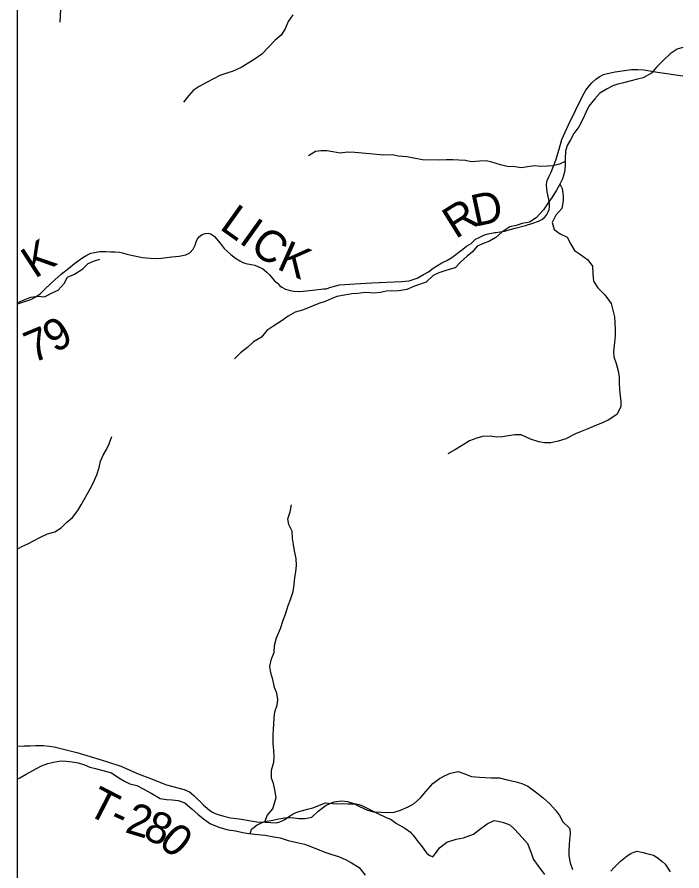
# Model space of a CAD drawing. Extents: x 0 to 82.7, y -0.2 to 22.
# Drawn here: x 2.1 to 3.292, y 15.035 to 16.567 of the extents above; entities that cross this region are included whole.
import ezdxf

# ---------------------------------------------------------------- set-up
doc = ezdxf.new("R2010")
doc.units = 0
for name, color, linetype in [('GM_X_County_Text', 7, 'Continuous'), ('GM_X_Minor_River', 7, 'Continuous'), ('GM_X_Township_Road', 7, 'Continuous'), ('GM_X_Township_Road_Text', 7, 'Continuous'), ('GM_X_Township_Text', 7, 'Continuous'), ('SH_Cut_Line', 7, 'Continuous'), ('SH_Data', 7, 'Continuous')]:
    doc.layers.add(name, color=color, linetype=linetype)

msp = doc.modelspace()

# ---------------------------------------------------------------- linework, layer by layer
at = {"layer": 'GM_X_Minor_River'}
for points in [[(2.3003, 16.7593), (2.2927, 16.7519), (2.2802, 16.7417), (2.2703, 16.7365), (2.2589, 16.7286), (2.2494, 16.718), (2.241, 16.7059), (2.2299, 16.6912), (2.2253, 16.6776), (2.2143, 16.664), (2.2033, 16.6576), (2.1918, 16.6436), (2.1865, 16.6338), (2.1834, 16.6232), (2.1795, 16.6084), (2.1772, 16.5944), (2.1778, 16.5808), (2.177, 16.5698), (2.1769, 16.558)], [(2.5945, 16.5714), (2.5857, 16.5593), (2.5807, 16.5465), (2.5735, 16.5351), (2.5628, 16.5257), (2.5507, 16.5136), (2.5385, 16.5008), (2.5248, 16.4914), (2.5123, 16.4832), (2.502, 16.4768), (2.4876, 16.4704), (2.4781, 16.4674), (2.4634, 16.4626), (2.4406, 16.4506), (2.4266, 16.4427), (2.4159, 16.4356), (2.4076, 16.4258), (2.3984, 16.4144)], [(3.2933, 16.5129), (3.2835, 16.51), (3.271, 16.5013), (3.2584, 16.4896), (3.2462, 16.4772), (3.2375, 16.467), (3.2223, 16.4584), (3.2125, 16.4562), (3.1984, 16.4524), (3.1871, 16.4495), (3.1772, 16.4469), (3.1678, 16.4439), (3.1579, 16.4387), (3.145, 16.4311), (3.1358, 16.4206), (3.1248, 16.4074), (3.1194, 16.3964), (3.1144, 16.3843), (3.1072, 16.3703), (3.0984, 16.3586), (3.0919, 16.3473), (3.0862, 16.3367), (3.0835, 16.3268), (3.0826, 16.3128), (3.0829, 16.3003), (3.0813, 16.2893), (3.0779, 16.2772), (3.0729, 16.2674), (3.0671, 16.2568), (3.0595, 16.2439), (3.0523, 16.2341), (3.0439, 16.2213), (3.0309, 16.2073), (3.0188, 16.1994), (3.0055, 16.1968), (2.9949, 16.1935), (2.9832, 16.1909), (2.9691, 16.1815), (2.9585, 16.1721), (2.9471, 16.165), (2.9376, 16.1616), (2.9251, 16.1564), (2.9167, 16.1462), (2.9072, 16.1386), (2.8947, 16.1277), (2.8852, 16.1172), (2.8704, 16.1131), (2.8564, 16.1082), (2.8457, 16.1034), (2.8336, 16.0917), (2.8123, 16.0842), (2.7987, 16.0786), (2.7847, 16.0764), (2.7624, 16.0758), (2.7514, 16.0732), (2.74, 16.0721), (2.7245, 16.0734), (2.7102, 16.0712), (2.7, 16.0705), (2.6867, 16.0683), (2.6731, 16.0657), (2.6628, 16.0616), (2.6522, 16.0567), (2.6412, 16.0534), (2.628, 16.0478), (2.6117, 16.0414), (2.5988, 16.0377), (2.5859, 16.0306), (2.5733, 16.0216), (2.5604, 16.0133), (2.5479, 16.0047), (2.538, 15.993), (2.524, 15.9843), (2.5137, 15.9753), (2.5004, 15.9647), (2.4897, 15.9542)], [(3.0827, 16.3082), (3.0724, 16.3034), (3.0606, 16.3004), (3.0508, 16.2997), (3.0383, 16.2994), (3.0285, 16.3002), (3.0148, 16.2984), (3.0046, 16.297), (2.9925, 16.2986), (2.9785, 16.2994), (2.9668, 16.3021), (2.9514, 16.3068), (2.9408, 16.3091), (2.9294, 16.3088), (2.9139, 16.3078), (2.9037, 16.3097), (2.892, 16.3106), (2.8811, 16.311), (2.8701, 16.3111), (2.858, 16.3108), (2.827, 16.3109), (2.8141, 16.3137), (2.7986, 16.3164), (2.7835, 16.318), (2.7733, 16.32), (2.7574, 16.3197), (2.7318, 16.3221), (2.7185, 16.3234), (2.7057, 16.3246), (2.6921, 16.3247), (2.6792, 16.3232), (2.666, 16.3256), (2.6554, 16.3272), (2.6448, 16.3276), (2.635, 16.3261), (2.6224, 16.3183)], [(3.0732, 16.268), (3.0774, 16.2597), (3.0792, 16.2468), (3.0791, 16.2374), (3.0764, 16.2237), (3.0661, 16.2116), (3.0592, 16.1988), (3.0626, 16.1863), (3.0735, 16.1782), (3.0863, 16.1725), (3.0926, 16.1599), (3.0994, 16.1485), (3.1099, 16.1412), (3.1235, 16.132), (3.1314, 16.1202), (3.132, 16.1066), (3.1335, 16.0937), (3.1409, 16.0815), (3.1537, 16.0689), (3.165, 16.0533), (3.1672, 16.0438), (3.1709, 16.0297), (3.1716, 16.0187), (3.1722, 16.0062), (3.1722, 15.9956), (3.171, 15.9831), (3.1694, 15.9671), (3.1701, 15.9577), (3.1738, 15.9459), (3.1778, 15.9326), (3.1797, 15.9212), (3.1796, 15.9113), (3.1799, 15.8988), (3.181, 15.8878), (3.1824, 15.8776), (3.1827, 15.8681), (3.1751, 15.8541), (3.1595, 15.8443), (3.1463, 15.8383), (3.1356, 15.8338), (3.1231, 15.8286), (3.1114, 15.8234), (3.1011, 15.8193), (3.0837, 15.8103), (3.0701, 15.8062), (3.0568, 15.8032), (3.0458, 15.8033), (3.0353, 15.8052), (3.0202, 15.8099), (3.0036, 15.8176), (2.9922, 15.8176), (2.9805, 15.8158), (2.9706, 15.814), (2.9593, 15.8137), (2.9483, 15.8156), (2.9343, 15.8146), (2.9241, 15.812), (2.9112, 15.8071), (2.8998, 15.7996), (2.8862, 15.7914), (2.8721, 15.7839)], [(2.1, 16.0547), (2.1111, 16.0593), (2.1247, 16.0645), (2.1369, 16.0667), (2.149, 16.0651), (2.1641, 16.073), (2.1736, 16.0775), (2.1843, 16.0892), (2.1904, 16.1005), (2.2029, 16.1061), (2.2177, 16.1155), (2.2276, 16.1253), (2.2371, 16.1291), (2.2481, 16.1328)], [(2.1, 15.6127), (2.1084, 15.6174), (2.119, 15.6219), (2.1296, 15.6275), (2.141, 15.6335), (2.1543, 15.6399), (2.1679, 15.6436), (2.1789, 15.6511), (2.1892, 15.6609), (2.1995, 15.6692), (2.209, 15.682), (2.2151, 15.6919), (2.2201, 15.7017), (2.2308, 15.7206), (2.2365, 15.7308), (2.243, 15.7459), (2.2469, 15.7588), (2.2496, 15.7702), (2.2542, 15.7811), (2.26, 15.7914), (2.2649, 15.8016), (2.2696, 15.8148)], [(2.5447, 15.1242), (2.5486, 15.1346), (2.5585, 15.1463), (2.5612, 15.1565), (2.5647, 15.1671), (2.5621, 15.1808), (2.5599, 15.1918), (2.5562, 15.2013), (2.5559, 15.2157), (2.5602, 15.2301), (2.561, 15.2403), (2.5603, 15.251), (2.5589, 15.2639), (2.5589, 15.2787), (2.5598, 15.2893), (2.5602, 15.2987), (2.561, 15.3101), (2.5619, 15.3204), (2.5661, 15.3325), (2.5673, 15.3427), (2.5658, 15.3541), (2.5617, 15.3644), (2.5584, 15.3788), (2.5551, 15.3906), (2.5529, 15.4023), (2.5564, 15.4156), (2.5606, 15.4269), (2.5615, 15.4395), (2.5653, 15.4535), (2.5722, 15.4701), (2.5772, 15.4853), (2.5811, 15.4958), (2.5861, 15.5117), (2.5903, 15.5223), (2.5949, 15.5363), (2.5965, 15.5489), (2.5977, 15.5614), (2.5997, 15.5716), (2.6009, 15.583), (2.6006, 15.5959), (2.5973, 15.6095), (2.5955, 15.6209), (2.5936, 15.6316), (2.593, 15.6448), (2.5874, 15.657), (2.5855, 15.6669), (2.5894, 15.6794), (2.5917, 15.6922)], [(2.1, 15.1999), (2.1051, 15.2021), (2.1161, 15.2085), (2.1282, 15.2156), (2.1438, 15.2235), (2.1551, 15.228), (2.1654, 15.2306), (2.1782, 15.2328), (2.1881, 15.2323), (2.1987, 15.2311), (2.2092, 15.2292), (2.2206, 15.2253), (2.2304, 15.2215), (2.2406, 15.2191), (2.2692, 15.2114), (2.2824, 15.2022), (2.2926, 15.1964), (2.3024, 15.1915), (2.3145, 15.1883), (2.3262, 15.1826), (2.3405, 15.1745), (2.3567, 15.1653), (2.368, 15.1634), (2.3779, 15.1626), (2.3888, 15.1617), (2.4005, 15.1575), (2.4137, 15.146), (2.4238, 15.1369), (2.434, 15.1288), (2.4468, 15.1197), (2.4634, 15.1131), (2.4785, 15.1088), (2.4913, 15.1069), (2.5049, 15.1041), (2.5155, 15.1022), (2.5318, 15.1006), (2.545, 15.0993), (2.5601, 15.0966), (2.5714, 15.0943), (2.5861, 15.0896), (2.6043, 15.0857), (2.6152, 15.0834), (2.6269, 15.0791), (2.6367, 15.0745), (2.6533, 15.068), (2.6643, 15.0649), (2.6764, 15.061), (2.6888, 15.0556), (2.6997, 15.0495), (2.7133, 15.0411), (2.7238, 15.0277)], [(2.5177, 15.102), (2.5205, 15.1101), (2.5304, 15.118), (2.5433, 15.124), (2.5557, 15.1254), (2.5694, 15.1284), (2.5796, 15.1302), (2.5917, 15.1309), (2.6049, 15.1293), (2.6166, 15.1293), (2.6284, 15.1318), (2.6398, 15.1424), (2.6542, 15.1529), (2.6686, 15.1589), (2.6815, 15.1607), (2.6921, 15.1595), (2.7038, 15.1564), (2.7136, 15.151), (2.7283, 15.1441), (2.7389, 15.1414), (2.7525, 15.1406), (2.7646, 15.1401), (2.7759, 15.1404), (2.7873, 15.1441), (2.8013, 15.1501), (2.8116, 15.1561), (2.823, 15.1663), (2.8329, 15.1776), (2.8451, 15.192), (2.8576, 15.201), (2.8675, 15.2062), (2.8769, 15.2107), (2.8909, 15.2137), (2.9008, 15.2102), (2.9147, 15.2048), (2.9291, 15.2036), (2.9389, 15.2028), (2.9502, 15.2023), (2.965, 15.2019), (2.9786, 15.1984), (2.9922, 15.1956), (3.005, 15.1921), (3.0156, 15.1875), (3.0295, 15.1772), (3.043, 15.1665), (3.0551, 15.1554), (3.0652, 15.1444), (3.0723, 15.1345), (3.0787, 15.1234), (3.0911, 15.1112), (3.0918, 15.1013), (3.0906, 15.0915), (3.0898, 15.0816), (3.089, 15.0722), (3.0889, 15.0623), (3.0915, 15.0498), (3.0956, 15.0376)]]:
    msp.add_lwpolyline(points, dxfattribs=at)
at = {"layer": 'GM_X_Township_Road'}
for points in [[(2.9586, 16.1808), (2.974, 16.1831), (2.9929, 16.1883), (3.0115, 16.1933), (3.0247, 16.1977), (3.0347, 16.2011), (3.0408, 16.204), (3.046, 16.2084), (3.0496, 16.2128), (3.0521, 16.2176), (3.0538, 16.2222), (3.0548, 16.2268), (3.0546, 16.2321), (3.0534, 16.2402), (3.0502, 16.2538), (3.0498, 16.2593), (3.0493, 16.2669), (3.0504, 16.2742), (3.0532, 16.2809), (3.0573, 16.289), (3.0657, 16.3104), (3.0718, 16.3303), (3.0768, 16.3474), (3.0888, 16.3738), (3.1135, 16.4253), (3.1197, 16.4362), (3.126, 16.4446), (3.1302, 16.4494), (3.1373, 16.4559), (3.1434, 16.4601), (3.1511, 16.4641), (3.1583, 16.4664), (3.1725, 16.4689), (3.2016, 16.4733), (3.2129, 16.4735), (3.2238, 16.4729), (3.2479, 16.4687), (3.2937, 16.462)], [(2.5672, 16.089), (2.5705, 16.0857), (2.5749, 16.0828), (2.5814, 16.0792), (2.5898, 16.0765), (2.5961, 16.0755), (2.6045, 16.075), (2.6126, 16.0757), (2.6298, 16.0775), (2.6495, 16.0796), (2.6543, 16.0796), (2.6627, 16.0826), (2.6715, 16.0851), (2.6782, 16.0868), (2.6878, 16.0876), (2.7054, 16.0884), (2.7359, 16.0905), (2.7891, 16.093), (2.796, 16.0933), (2.8027, 16.0941), (2.8099, 16.0962), (2.817, 16.0989), (2.8289, 16.1052), (2.8377, 16.1104), (2.8459, 16.1165), (2.8538, 16.1215), (2.8616, 16.1262), (2.8704, 16.1307), (2.8775, 16.1345), (2.8844, 16.1393), (2.8919, 16.1452), (2.8991, 16.1508), (2.906, 16.1565), (2.9141, 16.1609), (2.922, 16.1687), (2.9296, 16.1724), (2.9382, 16.1764), (2.9443, 16.1785), (2.9504, 16.1793), (2.9566, 16.1806), (2.9586, 16.1808)], [(2.1, 16.0519), (2.1045, 16.0537), (2.1244, 16.0608), (2.1336, 16.0654), (2.1413, 16.0706), (2.1493, 16.0782), (2.1612, 16.0897), (2.1675, 16.096), (2.1788, 16.1062), (2.193, 16.1167), (2.2031, 16.1251), (2.2177, 16.136), (2.2249, 16.1404), (2.2322, 16.1435), (2.2389, 16.145), (2.2477, 16.1464), (2.259, 16.1469), (2.268, 16.1462), (2.2753, 16.146), (2.2839, 16.1454), (2.2891, 16.1445), (2.2965, 16.1422), (2.3073, 16.1397), (2.3247, 16.1362), (2.3394, 16.1345), (2.3492, 16.1341), (2.3582, 16.1345), (2.3676, 16.1362), (2.3777, 16.1374), (2.3907, 16.1383), (2.4024, 16.141), (2.4099, 16.1441), (2.4154, 16.151), (2.4194, 16.158), (2.4208, 16.164), (2.4233, 16.1695), (2.4273, 16.1739), (2.4321, 16.1772), (2.4372, 16.1787), (2.4426, 16.1793), (2.4474, 16.1785), (2.4539, 16.1737), (2.4642, 16.1619), (2.4711, 16.1521), (2.4832, 16.1416), (2.4916, 16.1347), (2.4991, 16.1301), (2.5046, 16.1272), (2.5102, 16.1253), (2.5194, 16.1236), (2.5261, 16.1221), (2.5331, 16.1194), (2.5398, 16.1159), (2.5437, 16.1129), (2.5479, 16.1096), (2.5527, 16.1048), (2.5617, 16.0941), (2.5666, 16.0897), (2.5672, 16.089)], [(2.1, 15.2588), (2.1125, 15.2594), (2.1236, 15.2594), (2.1333, 15.2603), (2.1472, 15.2601), (2.1575, 15.259), (2.1666, 15.2578), (2.1735, 15.2562), (2.2071, 15.2475), (2.237, 15.2384), (2.26, 15.2318), (2.2857, 15.2231), (2.317, 15.2095), (2.3391, 15.2012), (2.368, 15.1899), (2.3882, 15.1843), (2.3995, 15.1812), (2.409, 15.177), (2.4169, 15.1705), (2.4225, 15.1651), (2.4292, 15.1584), (2.4345, 15.1533), (2.4405, 15.1479), (2.4458, 15.1436), (2.4514, 15.1402), (2.4551, 15.1384), (2.4607, 15.1365), (2.4704, 15.1333), (2.4826, 15.1303), (2.4979, 15.1285), (2.5297, 15.1234), (2.5448, 15.1226), (2.5652, 15.1216), (2.5709, 15.1232), (2.5764, 15.1254), (2.58, 15.1273), (2.5847, 15.1311), (2.5893, 15.1341), (2.595, 15.1378), (2.6032, 15.1414), (2.6142, 15.1442), (2.6208, 15.146), (2.6301, 15.1485), (2.653, 15.1574), (2.6586, 15.1568), (2.6655, 15.1564), (2.6726, 15.1558), (2.6827, 15.156), (2.6932, 15.1558), (2.7073, 15.1553), (2.7124, 15.1543), (2.7181, 15.1523), (2.7468, 15.1384), (2.7607, 15.1317), (2.7708, 15.1273), (2.7805, 15.1202), (2.7951, 15.1117), (2.8052, 15.1046), (2.8073, 15.1024)], [(2.8073, 15.1024), (2.8102, 15.0994), (2.8187, 15.0882), (2.8242, 15.0808), (2.8341, 15.0674), (2.8385, 15.0634), (2.8454, 15.0605), (2.8517, 15.0686), (2.8571, 15.0765), (2.8703, 15.0866), (2.887, 15.0923), (2.9006, 15.0943), (2.9184, 15.1012), (2.9269, 15.1078), (2.9428, 15.1198), (2.9556, 15.1256), (2.9627, 15.1244), (2.9719, 15.1222), (2.9833, 15.1177), (2.991, 15.1109), (2.9994, 15.1018), (3.0055, 15.0949), (3.015, 15.0842), (3.0203, 15.0707), (3.0261, 15.0559), (3.0338, 15.0446), (3.0453, 15.0288)], [(3.1644, 15.0347), (3.1704, 15.0415), (3.1816, 15.0525), (3.1937, 15.062), (3.2002, 15.0662), (3.206, 15.0686), (3.2115, 15.0704), (3.2173, 15.0696), (3.2222, 15.0684), (3.2285, 15.0662), (3.2343, 15.065), (3.242, 15.063), (3.2501, 15.0575), (3.2568, 15.0521), (3.262, 15.047), (3.2665, 15.0403), (3.2709, 15.0335)]]:
    msp.add_lwpolyline(points, dxfattribs=at)
at = {"layer": 'GM_X_Township_Text'}
msp.add_lwpolyline([(2.1, 19.5964), (2.1, 14.1), (2.4652, 14.1), (3.1288, 14.3932), (3.6092, 14.6054), (3.7187, 14.6543), (4.1209, 14.8338), (3.8036, 15.5496), (3.6125, 15.9807), (3.4071, 16.476), (3.2909, 16.7562), (3.0556, 17.2782), (3.0279, 17.3486), (2.7199, 18.1299), (2.4438, 18.782), (2.397, 18.8926), (2.3145, 19.0873), (2.2742, 19.1826)], close=True, dxfattribs=at)
at = {"layer": 'SH_Cut_Line'}
msp.add_lwpolyline([(4.1209, 14.8338), (3.8036, 15.5496), (3.6125, 15.9807), (3.4071, 16.476), (3.2909, 16.7562), (3.0556, 17.2782), (3.0279, 17.3486), (2.7199, 18.1299), (2.7784, 18.9951), (2.7788, 19.0007), (2.8288, 19.7415), (2.8645, 20.2693), (2.8645, 20.2703), (2.8651, 20.279), (2.884, 20.5583), (3.179, 20.5374), (3.6288, 20.5056), (5.9672, 20.3493), (5.9756, 20.3782), (6.1272, 20.9), (2.1, 20.9), (2.1, 14.1)], dxfattribs=at)
at = {"layer": 'SH_Data'}
msp.add_line((2.1, 20.9), (2.1, 14.1), dxfattribs=at)

# ---------------------------------------------------------------- texts
at = {"layer": 'GM_X_County_Text'}
msp.add_text('SCIOTO COUNTY', height=0.189394, rotation=23.8999, dxfattribs=at).set_placement((2.2092, 14.142))
at = {"layer": 'GM_X_Township_Road_Text'}
for s, rotation, p in [('D', 12.1894, (2.9211, 16.191)), ('L', 324.5136, (2.4612, 16.1882)), ('R', 31.9123, (2.8862, 16.1683)), ('I', 324.4932, (2.4958, 16.1636)), ('C', 323.963, (2.5147, 16.1501)), ('K', 32.8784, (2.1319, 16.0971)), ('K', 335.8868, (2.5636, 16.1162)), ('9', 31.1942, (2.1683, 15.9634)), ('7', 22.6755, (2.1278, 15.9457)), ('T', 332.8753, (2.2222, 15.1383)), ('2', 343.2389, (2.2916, 15.105)), ('-', 335.4889, (2.2625, 15.1177)), ('8', 335.1387, (2.3231, 15.0957)), ('0', 319.3369, (2.3514, 15.0832))]:
    msp.add_text(s, height=0.0568, rotation=rotation, dxfattribs=at).set_placement(p)

doc.saveas('drawing.dxf')
